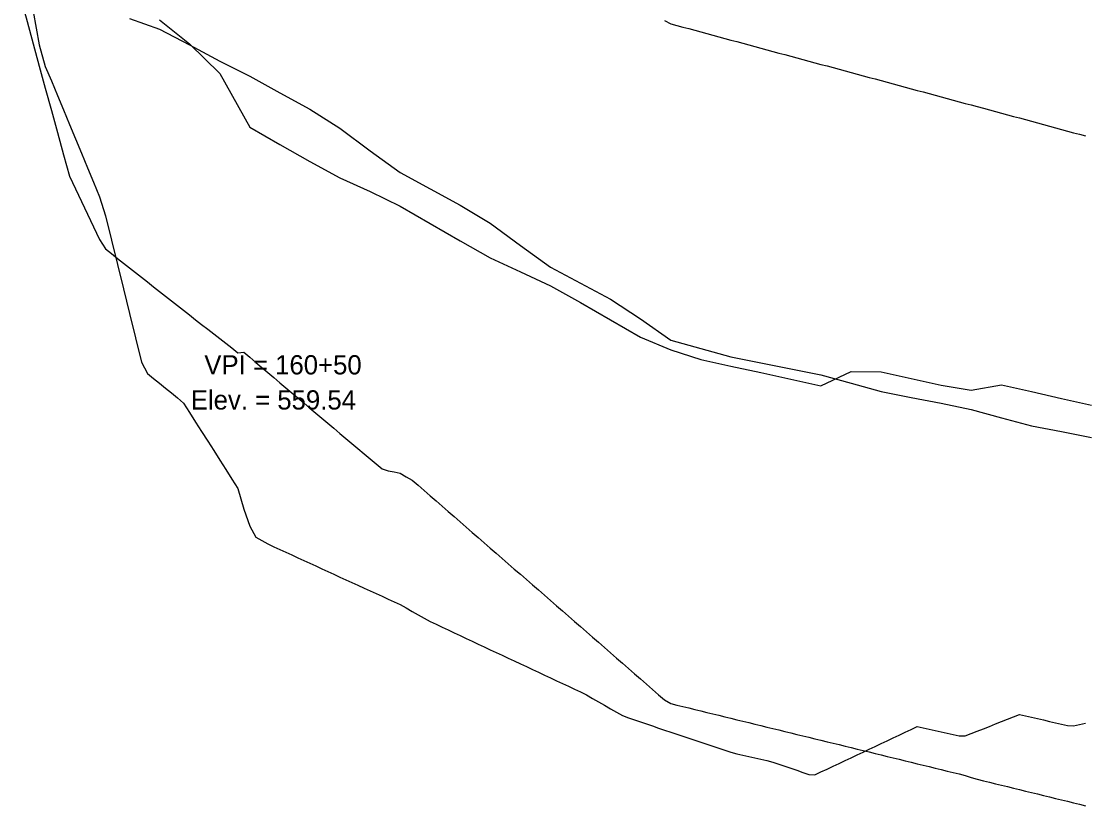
# Model space of a CAD drawing. Extents: x 1733571 to 1737171, y 1214895 to 1219895.
# Drawn here: x 1735184 to 1735360.8, y 1217839.1 to 1217969.6 of the extents above; entities that cross this region are included whole.
import ezdxf

# ---------------------------------------------------------------- set-up
doc = ezdxf.new("R2010")
doc.units = 0
for name, color, linetype in [('RD_DDB_Profile_EX', 7, 'Continuous'), ('RD_DDB_Profile_Lbl', 7, 'Continuous'), ('RD_Sketch1', 7, 'Continuous'), ('RD_Sketch2', 7, 'Continuous'), ('RD_Sketch3', 7, 'Continuous'), ('RD_Sketch4', 7, 'Continuous')]:
    doc.layers.add(name, color=color, linetype=linetype)

msp = doc.modelspace()

# ---------------------------------------------------------------- linework, layer by layer
at = {"layer": 'RD_DDB_Profile_EX'}
for points in [[(1735290.9887, 1217969.74464), (1735291.9887, 1217969.19636), (1735292.9887, 1217968.92616), (1735293.9887, 1217968.65596), (1735294.9887, 1217968.38576), (1735295.9887, 1217968.11556), (1735296.9887, 1217967.84536), (1735297.9887, 1217967.57516), (1735298.9887, 1217967.30496), (1735299.9887, 1217967.03476), (1735300.9887, 1217966.76456), (1735301.9887, 1217966.49436), (1735302.9887, 1217966.22416), (1735303.9887, 1217965.95396)], [(1735303.9887, 1217965.95396), (1735304.9887, 1217965.68376), (1735305.9887, 1217965.41356), (1735306.9887, 1217965.14336), (1735307.9887, 1217964.87316), (1735308.9887, 1217964.60296), (1735309.9887, 1217964.33276), (1735310.9887, 1217964.06256), (1735311.9887, 1217963.79236), (1735312.9887, 1217963.52217), (1735313.9887, 1217963.25197), (1735314.9887, 1217962.98177), (1735315.9887, 1217962.71157), (1735316.9887, 1217962.44727), (1735317.9887, 1217962.17688), (1735318.9887, 1217961.90649), (1735319.9887, 1217961.6361), (1735320.9887, 1217961.36571), (1735321.9887, 1217961.09533), (1735322.9887, 1217960.82494), (1735323.9887, 1217960.55455), (1735324.9887, 1217960.28416), (1735325.9887, 1217960.01377), (1735326.9887, 1217959.74339), (1735327.9887, 1217959.473), (1735328.9887, 1217959.20261), (1735329.9887, 1217958.93222), (1735330.9887, 1217958.66183), (1735331.9887, 1217958.39144), (1735332.9887, 1217958.12106), (1735333.9887, 1217957.85067), (1735334.9887, 1217957.58028), (1735335.9887, 1217957.30989), (1735336.9887, 1217957.0395), (1735337.9887, 1217956.76911), (1735338.9887, 1217956.49873), (1735339.9887, 1217956.22834), (1735340.9887, 1217955.95795), (1735341.9887, 1217955.68877), (1735342.9887, 1217955.41819), (1735343.9887, 1217955.14761), (1735344.9887, 1217954.87703), (1735345.9887, 1217954.60645), (1735346.9887, 1217954.33587), (1735347.9887, 1217954.06529), (1735348.9887, 1217953.79392), (1735349.9887, 1217953.52223), (1735350.9887, 1217953.25054), (1735351.9887, 1217952.97885), (1735352.9887, 1217952.70716), (1735353.9887, 1217952.43547), (1735354.9887, 1217952.16378), (1735355.9887, 1217951.89209), (1735356.9887, 1217951.62039), (1735357.9887, 1217951.3487), (1735358.9887, 1217951.07701), (1735359.9887, 1217950.80532), (1735360.9887, 1217950.53363)]]:
    msp.add_lwpolyline(points, dxfattribs=at)
at = {"layer": 'RD_Sketch1'}
for points in [[(1735183.9887, 1217973.24941), (1735184.9887, 1217969.55522), (1735185.9887, 1217965.86103), (1735186.9887, 1217962.16684), (1735187.9887, 1217958.47266), (1735188.9887, 1217954.77847), (1735189.9887, 1217951.08428), (1735190.9887, 1217947.3901), (1735191.9887, 1217943.83077), (1735192.9887, 1217941.72844), (1735193.9887, 1217939.62612), (1735194.9887, 1217937.52379), (1735195.9887, 1217935.42147), (1735196.9887, 1217933.31914), (1735197.9887, 1217931.73017), (1735198.9887, 1217930.94545), (1735199.9887, 1217930.16074), (1735200.9887, 1217929.37602), (1735201.9887, 1217928.5913), (1735202.9887, 1217927.80659), (1735203.9887, 1217927.02187), (1735204.9887, 1217926.23715), (1735205.9887, 1217925.45243)], [(1735205.9887, 1217925.45243), (1735206.9887, 1217924.66772), (1735207.9887, 1217923.883), (1735208.9887, 1217923.09828), (1735209.9887, 1217922.31357), (1735210.9887, 1217921.52885), (1735211.9887, 1217920.74413), (1735212.9887, 1217919.95941), (1735213.9887, 1217919.1747), (1735214.9887, 1217918.38998), (1735215.9887, 1217917.60526), (1735216.9887, 1217916.82055), (1735217.9887, 1217916.03583), (1735218.9887, 1217915.25111), (1735219.9887, 1217914.46639), (1735220.9887, 1217914.54121), (1735221.9887, 1217913.69718), (1735222.9887, 1217912.85315), (1735223.9887, 1217912.00912), (1735224.9887, 1217911.16509), (1735225.9887, 1217910.32106), (1735226.9887, 1217909.47703), (1735227.9887, 1217908.63299), (1735228.9887, 1217907.78896), (1735229.9887, 1217906.94493), (1735230.9887, 1217906.1009), (1735231.9887, 1217905.25687), (1735232.9887, 1217904.41284), (1735233.9887, 1217903.56881), (1735234.9887, 1217902.72478), (1735235.9887, 1217901.88075), (1735236.9887, 1217901.03672), (1735237.9887, 1217900.19269), (1735238.9887, 1217899.34866), (1735239.9887, 1217898.50463), (1735240.9887, 1217897.6606), (1735241.9887, 1217896.81656), (1735242.9887, 1217895.97253), (1735243.9887, 1217895.1285), (1735244.9887, 1217894.79513), (1735245.9887, 1217894.64006), (1735246.9887, 1217894.39257), (1735247.9887, 1217893.83229), (1735248.9887, 1217893.27202), (1735249.9887, 1217892.41999), (1735250.9887, 1217891.54394), (1735251.9887, 1217890.67245), (1735252.9887, 1217889.80096), (1735253.9887, 1217888.92947), (1735254.9887, 1217888.05797), (1735255.9887, 1217887.18648), (1735256.9887, 1217886.31499), (1735257.9887, 1217885.4435), (1735258.9887, 1217884.57201), (1735259.9887, 1217883.70052), (1735260.9887, 1217882.82903), (1735261.9887, 1217881.95754), (1735262.9887, 1217881.08604), (1735263.9887, 1217880.21455), (1735264.9887, 1217879.34306), (1735265.9887, 1217878.47157), (1735266.9887, 1217877.60008), (1735267.9887, 1217876.72859), (1735268.9887, 1217875.8571), (1735269.9887, 1217874.98561), (1735270.9887, 1217874.11411), (1735271.9887, 1217873.24262), (1735272.9887, 1217872.37113), (1735273.9887, 1217871.49964), (1735274.9887, 1217870.62815), (1735275.9887, 1217869.75666), (1735276.9887, 1217868.88517), (1735277.9887, 1217868.01368), (1735278.9887, 1217867.14218), (1735279.9887, 1217866.27069), (1735280.9887, 1217865.3992), (1735281.9887, 1217864.52771), (1735282.9887, 1217863.65622), (1735283.9887, 1217862.78473), (1735284.9887, 1217861.91324), (1735285.9887, 1217861.04174), (1735286.9887, 1217860.17025), (1735287.9887, 1217859.29876), (1735288.9887, 1217858.42727), (1735289.9887, 1217857.55578), (1735290.9887, 1217856.68429), (1735291.9887, 1217856.08471), (1735292.9887, 1217855.84055), (1735293.9887, 1217855.59639), (1735294.9887, 1217855.35224), (1735295.9887, 1217855.10808), (1735296.9887, 1217854.86392), (1735297.9887, 1217854.61977), (1735298.9887, 1217854.37561), (1735299.9887, 1217854.13145), (1735300.9887, 1217853.8873), (1735301.9887, 1217853.64314), (1735302.9887, 1217853.39898), (1735303.9887, 1217853.15483), (1735304.9887, 1217852.91067), (1735305.9887, 1217852.66651)], [(1735305.9887, 1217852.66651), (1735306.9887, 1217852.42236), (1735307.9887, 1217852.1782), (1735308.9887, 1217851.93404), (1735309.9887, 1217851.68989), (1735310.9887, 1217851.44573), (1735311.9887, 1217851.20158), (1735312.9887, 1217850.95742), (1735313.9887, 1217850.71326), (1735314.9887, 1217850.46911), (1735315.9887, 1217850.22495), (1735316.9887, 1217849.98079), (1735317.9887, 1217849.73664), (1735318.9887, 1217849.49248), (1735319.9887, 1217849.24832), (1735320.9887, 1217849.00417), (1735321.9887, 1217848.76001), (1735322.9887, 1217848.51585), (1735323.9887, 1217848.2717), (1735324.9887, 1217848.02754), (1735325.9887, 1217847.78338), (1735326.9887, 1217847.53923), (1735327.9887, 1217847.29507), (1735328.9887, 1217847.05091), (1735329.9887, 1217846.80676), (1735330.9887, 1217846.5626), (1735331.9887, 1217846.31844), (1735332.9887, 1217846.07429), (1735333.9887, 1217845.83013), (1735334.9887, 1217845.58597), (1735335.9887, 1217845.34182), (1735336.9887, 1217845.09766), (1735337.9887, 1217844.8535), (1735338.9887, 1217844.60935), (1735339.9887, 1217844.36519), (1735340.9887, 1217844.08891), (1735341.9887, 1217843.80496), (1735342.9887, 1217843.521), (1735343.9887, 1217843.23987), (1735344.9887, 1217842.99509), (1735345.9887, 1217842.75032), (1735346.9887, 1217842.50554), (1735347.9887, 1217842.26076), (1735348.9887, 1217842.01598), (1735349.9887, 1217841.7712), (1735350.9887, 1217841.52642), (1735351.9887, 1217841.28164), (1735352.9887, 1217841.03686), (1735353.9887, 1217840.79208), (1735354.9887, 1217840.54731), (1735355.9887, 1217840.30253), (1735356.9887, 1217840.05775), (1735357.9887, 1217839.81297), (1735358.9887, 1217839.56819), (1735359.9887, 1217839.32341), (1735360.9887, 1217839.07863)]]:
    msp.add_lwpolyline(points, dxfattribs=at)
at = {"layer": 'RD_Sketch2'}
for points in [[(1735185.9887, 1217971.261), (1735186.9887, 1217965.70452), (1735187.9887, 1217962.09782), (1735188.9887, 1217959.68871), (1735189.9887, 1217957.27961), (1735190.9887, 1217954.8705), (1735191.9887, 1217952.4614), (1735192.9887, 1217950.0523), (1735193.9887, 1217947.64319), (1735194.9887, 1217945.23409), (1735195.9887, 1217942.82498), (1735196.9887, 1217940.41588), (1735197.9887, 1217937.26095), (1735198.9887, 1217933.19819), (1735199.9887, 1217929.13543)], [(1735199.9887, 1217929.13543), (1735200.9887, 1217925.07268), (1735201.9887, 1217921.00992), (1735202.9887, 1217916.94716), (1735203.9887, 1217912.8844), (1735204.9887, 1217911.00165), (1735205.9887, 1217910.19788), (1735206.9887, 1217909.39412), (1735207.9887, 1217908.59036), (1735208.9887, 1217907.78659), (1735209.9887, 1217906.98283), (1735210.9887, 1217906.07963), (1735211.9887, 1217904.49975), (1735212.9887, 1217902.91988), (1735213.9887, 1217901.34), (1735214.9887, 1217899.76012), (1735215.9887, 1217898.18024), (1735216.9887, 1217896.60036), (1735217.9887, 1217895.02049), (1735218.9887, 1217893.44061), (1735219.9887, 1217891.86073), (1735220.9887, 1217888.42128), (1735221.9887, 1217885.61154), (1735222.9887, 1217883.76618), (1735223.9887, 1217883.1971), (1735224.9887, 1217882.64237), (1735225.9887, 1217882.18371), (1735226.9887, 1217881.72506), (1735227.9887, 1217881.2664), (1735228.9887, 1217880.80775), (1735229.9887, 1217880.34909), (1735230.9887, 1217879.89044), (1735231.9887, 1217879.43178), (1735232.9887, 1217878.97313), (1735233.9887, 1217878.51447), (1735234.9887, 1217878.05582), (1735235.9887, 1217877.59716), (1735236.9887, 1217877.13851), (1735237.9887, 1217876.67985), (1735238.9887, 1217876.2212), (1735239.9887, 1217875.76254), (1735240.9887, 1217875.30389), (1735241.9887, 1217874.84523), (1735242.9887, 1217874.38658), (1735243.9887, 1217873.92793), (1735244.9887, 1217873.46927), (1735245.9887, 1217873.01062), (1735246.9887, 1217872.55196), (1735247.9887, 1217871.98877), (1735248.9887, 1217871.41713), (1735249.9887, 1217870.84548), (1735250.9887, 1217870.27384), (1735251.9887, 1217869.73746), (1735252.9887, 1217869.26849), (1735253.9887, 1217868.79952), (1735254.9887, 1217868.33055), (1735255.9887, 1217867.86158), (1735256.9887, 1217867.39262), (1735257.9887, 1217866.92365), (1735258.9887, 1217866.45468), (1735259.9887, 1217865.98571), (1735260.9887, 1217865.51674), (1735261.9887, 1217865.04777), (1735262.9887, 1217864.5788), (1735263.9887, 1217864.10983), (1735264.9887, 1217863.64087), (1735265.9887, 1217863.1719), (1735266.9887, 1217862.70293), (1735267.9887, 1217862.23396), (1735268.9887, 1217861.76499), (1735269.9887, 1217861.29602), (1735270.9887, 1217860.82705), (1735271.9887, 1217860.35808), (1735272.9887, 1217859.88912), (1735273.9887, 1217859.42015), (1735274.9887, 1217858.95118), (1735275.9887, 1217858.48221), (1735276.9887, 1217858.01324), (1735277.9887, 1217857.5203), (1735278.9887, 1217856.94577), (1735279.9887, 1217856.37124), (1735280.9887, 1217855.79671), (1735281.9887, 1217855.22218), (1735282.9887, 1217854.64765), (1735283.9887, 1217854.07311), (1735284.9887, 1217853.69312), (1735285.9887, 1217853.35746), (1735286.9887, 1217853.02179), (1735287.9887, 1217852.68613), (1735288.9887, 1217852.35047), (1735289.9887, 1217852.0148), (1735290.9887, 1217851.67914), (1735291.9887, 1217851.34347), (1735292.9887, 1217851.00781), (1735293.9887, 1217850.67215), (1735294.9887, 1217850.33648), (1735295.9887, 1217850.00082), (1735296.9887, 1217849.66515), (1735297.9887, 1217849.32949), (1735298.9887, 1217848.99382), (1735299.9887, 1217848.65816)], [(1735299.9887, 1217848.65816), (1735300.9887, 1217848.3225), (1735301.9887, 1217847.98683), (1735302.9887, 1217847.69318), (1735303.9887, 1217847.47536), (1735304.9887, 1217847.25754), (1735305.9887, 1217847.03972), (1735306.9887, 1217846.82191), (1735307.9887, 1217846.60409), (1735308.9887, 1217846.34744), (1735309.9887, 1217846.00432), (1735310.9887, 1217845.6612), (1735311.9887, 1217845.31807), (1735312.9887, 1217844.97495), (1735313.9887, 1217844.63183), (1735314.9887, 1217844.28871), (1735315.9887, 1217844.24117), (1735316.9887, 1217844.71157), (1735317.9887, 1217845.18197), (1735318.9887, 1217845.65236), (1735319.9887, 1217846.12276), (1735320.9887, 1217846.59316), (1735321.9887, 1217847.06355), (1735322.9887, 1217847.53395), (1735323.9887, 1217848.00435), (1735324.9887, 1217848.47475), (1735325.9887, 1217848.94514), (1735326.9887, 1217849.41554), (1735327.9887, 1217849.88594), (1735328.9887, 1217850.35633), (1735329.9887, 1217850.82673), (1735330.9887, 1217851.29713), (1735331.9887, 1217851.76752), (1735332.9887, 1217852.23792), (1735333.9887, 1217852.05249), (1735334.9887, 1217851.83088), (1735335.9887, 1217851.60927), (1735336.9887, 1217851.38765), (1735337.9887, 1217851.16604), (1735338.9887, 1217850.94443), (1735339.9887, 1217850.72281), (1735340.9887, 1217850.69142), (1735341.9887, 1217851.09016), (1735342.9887, 1217851.48891), (1735343.9887, 1217851.88766), (1735344.9887, 1217852.2864), (1735345.9887, 1217852.68515), (1735346.9887, 1217853.08389), (1735347.9887, 1217853.48264), (1735348.9887, 1217853.88139), (1735349.9887, 1217854.24117), (1735350.9887, 1217854.01759), (1735351.9887, 1217853.794), (1735352.9887, 1217853.57042), (1735353.9887, 1217853.34684), (1735354.9887, 1217853.12326), (1735355.9887, 1217852.89967), (1735356.9887, 1217852.67609), (1735357.9887, 1217852.45251), (1735358.9887, 1217852.39618), (1735359.9887, 1217852.59901), (1735360.9887, 1217852.80184)]]:
    msp.add_lwpolyline(points, dxfattribs=at)
at = {"layer": 'RD_Sketch3'}
msp.add_lwpolyline([(1735201.9887, 1217970.09506), (1735206.9887, 1217968.32019), (1735211.9887, 1217965.72206), (1735216.9887, 1217962.98839), (1735221.9887, 1217960.45364), (1735226.9887, 1217957.72224), (1735231.9887, 1217954.99085), (1735236.9887, 1217951.81209), (1735241.9887, 1217948.07436), (1735246.9887, 1217944.42457), (1735251.9887, 1217941.72021), (1735256.9887, 1217939.01585), (1735261.9887, 1217935.99272), (1735266.9887, 1217932.29226), (1735271.9887, 1217928.71209), (1735276.9887, 1217926.03422), (1735281.9887, 1217923.35634), (1735286.9887, 1217920.12254), (1735291.9887, 1217916.54598), (1735296.9887, 1217915.16556), (1735301.9887, 1217913.78658), (1735306.9887, 1217912.78501), (1735311.9887, 1217911.78343), (1735316.9887, 1217910.76632), (1735321.9887, 1217909.38263), (1735326.9887, 1217908.02593), (1735331.9887, 1217907.0353), (1735336.9887, 1217906.04466), (1735341.9887, 1217905.03772), (1735346.9887, 1217903.65052), (1735351.9887, 1217902.3198), (1735356.9887, 1217901.34097), (1735361.9887, 1217900.36213)], dxfattribs=at)
at = {"layer": 'RD_Sketch4'}
msp.add_lwpolyline([(1735206.9887, 1217969.86147), (1735211.9887, 1217965.84265), (1735216.9887, 1217960.92061), (1735221.9887, 1217951.97964), (1735226.9887, 1217949.13421), (1735231.9887, 1217946.28878), (1735236.9887, 1217943.56858), (1735241.9887, 1217941.2753), (1735246.9887, 1217938.82158), (1735251.9887, 1217935.96336), (1735256.9887, 1217933.10515), (1735261.9887, 1217930.25963), (1735266.9887, 1217927.91478), (1735271.9887, 1217925.56994), (1735276.9887, 1217922.7934), (1735281.9887, 1217919.92074), (1735286.9887, 1217917.04809), (1735291.9887, 1217914.9302), (1735296.9887, 1217913.32565), (1735301.9887, 1217912.23656), (1735306.9887, 1217911.14747), (1735311.9887, 1217910.05839), (1735316.9887, 1217908.97948), (1735321.9887, 1217911.33147), (1735326.9887, 1217911.25882), (1735331.9887, 1217910.15075), (1735336.9887, 1217909.04268), (1735341.9887, 1217908.24482), (1735346.9887, 1217909.10551), (1735351.9887, 1217907.98759), (1735356.9887, 1217906.86968), (1735361.9887, 1217905.75176)], dxfattribs=at)

# ---------------------------------------------------------------- texts
at = {"layer": 'RD_DDB_Profile_Lbl'}
for s, p in [('VPI = 160+50', (1735214.43075, 1217910.8522)), ('Elev. = 559.54', (1735212.17793, 1217905.00938))]:
    msp.add_text(s, height=3.2, dxfattribs=at).set_placement(p)

doc.saveas('drawing.dxf')
